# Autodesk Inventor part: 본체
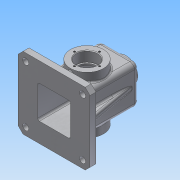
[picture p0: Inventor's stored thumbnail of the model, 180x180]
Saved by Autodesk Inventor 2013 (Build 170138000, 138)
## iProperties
Created: 2018-10
Part Number: 본체
Material: 알루미늄 6061
Document SubType Name: Modeling
Designer: Administrator
Density: 2.71 g/cm^3
Mass: 797.172 g
Surface Area: 899.5 cm^2
Volume: 294.159 cm^3
Author: Administrator
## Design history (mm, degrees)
sketch "스케치1"
  geometry: L1 (-32.5, -32.5)-(32.5, -32.5); L2 (32.5, -32.5)-(32.5, 32.5); L3 (32.5, 32.5)-(-32.5, 32.5); L4 (-32.5, 32.5)-(-32.5, -32.5); L5 (-32.5, -32.5)-(32.5, 32.5); L6 (32.5, -32.5)-(-32.5, 32.5); 1 further point
  constraints: 12 end point, 2 midpoint, 2 parallel, 1 horizontal, 1 perpendicular
  dimensions: "d0" = 65 distance of L3.end L2.end; "d1" = 65 distance of L2.end L1.end
extrude "돌출1" new body sketch "스케치1" stored distance "d2" = 110; taper "d3" = 0 deg
sketch "스케치2"
  geometry: L1 (-27.5, -27.5)-(27.5, -27.5); L2 (27.5, -27.5)-(27.5, 27.5); L3 (27.5, 27.5)-(-27.5, 27.5); L4 (-27.5, 27.5)-(-27.5, -27.5); L5 (-27.5, -27.5)-(27.5, 27.5); L6 (27.5, -27.5)-(-27.5, 27.5); 1 further point
  constraints: 12 end point, 2 midpoint, 2 parallel, 1 horizontal, 1 perpendicular
  dimensions: "d4" = 55 distance of L3.end L2.end; "d5" = 55 distance of L1.end L2.end
extrude "돌출2" cut sketch "스케치2" distance "d6" = 105; taper "d7" = 0 deg
node "작업 평면1"
sketch "스케치3"
  geometry: C1 r 20 at (0, 0); 1 further point
  constraints: 1 centre point, 1 coincident
  dimensions: "d9" = 40 diameter of C1
extrude "돌출3" join sketch "스케치3" stored distance "d10" = 105; taper "d11" = 7 deg
fillet "모깎기2" dims "d13" = 8
fillet "모깎기3" dims "d14" = 3
fillet "모깎기4" dims "d15" = 3
hole "구멍1" diameter "d18" = 22.835; stored, may be unused: countersink angle "d22" = 90 deg, drill point angle "d24" = 118 deg; dims "d16" = 10, "d17" = 10, "d19" = 6, "d20" = 4, "d21" = 2, "d23" = 8
sketch "스케치8"
  geometry: C1 r 27.5 at (32.5, 55); 1 further point
  constraints: 1 centre point, 1 coincident
  dimensions: "d45" = 55 diameter of C1
extrude "돌출7" join sketch "스케치8" distance "d46" = 15; taper "d47" = 0 deg
hole "구멍4" diameter "d59" = 30; stored, may be unused: countersink angle "d63" = 90 deg, drill point angle "d65" = 0 deg; dims "d57" = 10, "d58" = 10, "d60" = 8, "d61" = 35, "d62" = 17, "d64" = 20
sketch "스케치9"
  geometry: C1 r 17.5 at (0, 0) reference; 1 further point
  constraints: 1 vertical alignment
  dimensions: "d66" = 21 distance of C1.centre point (0, 21)
hole "구멍5" sketch "스케치9" at (0, 21) diameter "d67" = 3.242; stored, may be unused: countersink angle "d71" = 90 deg, drill point angle "d73" = 118 deg; dims "d68" = 8, "d69" = 35, "d70" = 17, "d72" = 10
sketch "스케치10"
  geometry: L1 (32.5, -32.5)-(32.5, 32.5) reference; L2 (32.5, 32.5)-(-32.5, 32.5) reference; L3 (-32.5, 32.5)-(-32.5, -32.5) reference; L4 (-32.5, -32.5)-(32.5, -32.5) reference; L5 (-60, -60)-(60, -60); L6 (60, -60)-(60, 60); L7 (60, 60)-(-60, 60); L8 (-60, 60)-(-60, -60); L9 (-60, -60)-(60, 60); L10 (60, -60)-(-60, 60); 1 further point
  constraints: 12 end point, 2 midpoint, 2 parallel, 1 horizontal, 1 perpendicular
  dimensions: "d77" = 120 distance of L7.end L6.end; "d78" = 120 distance of L6.end L5.end
extrude "돌출8" join sketch "스케치10" distance "d79" = 10; taper "d80" = 0 deg
chamfer "모따기1" distance "d81" = 8; stored, may be unused: second distance "d82" = 2, angle "d83" = 45 deg
sketch "스케치12"
  geometry: L1 (44.625, -25.86)-(48, -45); L2 (52, -45)-(60, -45) reference; L3 (52, -45)-(-52, -45) reference; L4 (24.5, 50)-(11.418, 50) reference; L5 (11.418, 50)-(11.418, 65) reference; L6 (11.418, 65)-(20, 65) reference; L7 (20, 65)-(21.228, 55) reference; L8 (21.228, 55)-(24.5, 55) reference; L9 (32.5, 47)-(32.5, -45) reference; L10 (32.5, -45)-(60, -45) reference; L11 (60, -45)-(60, -55) reference; L12 (60, -55)-(27.5, -55) reference; L13 (27.5, -55)-(27.5, 47) reference; L14 (-24.5, 55)-(-21.228, 55) reference; L15 (-21.228, 55)-(-20, 65) reference; L16 (-20, 65)-(-11.418, 65) reference; L17 (-11.418, 65)-(-11.418, 50) reference; L18 (-11.418, 50)-(-24.5, 50) reference; L19 (-27.5, 47)-(-27.5, -55) reference; L20 (-27.5, -55)-(-60, -55) reference; L21 (-60, -55)-(-60, -45) reference; L22 (-60, -45)-(-32.5, -45) reference; L23 (-32.5, -45)-(-32.5, 47) reference; A1 r 3 centre (24.5, 47) between (27.5, 47) and (24.5, 50) reference; A2 r 8 centre (24.5, 47) between (32.5, 47) and (24.5, 55) reference; A3 r 8 centre (-24.5, 47) between (-24.5, 55) and (-32.5, 47) reference; A4 r 3 centre (-24.5, 47) between (-24.5, 50) and (-27.5, 47) reference; 1 further point
  constraints: 2 end point, 1 point on line
  dimensions: "d89" = 12 horizontal distance of L11.end L1.end; "d90" = 10 deg angle of L11 L1
feature "리브1" sketch "스케치12" dims "d91" = 1, "d92" = 10, "d93" = 0, "d94" = 0, "d95" = 1, "d96" = 1
sketch "스케치13"
  geometry: L1 (-35.906, 42.5)-(-41.908, 42.5); L2 (-17.5, 30.5)-(-15, 30.5) reference; L3 (-15, 30.5)-(-15, 27.5) reference; L4 (-15, 27.5)-(-55, 27.5) reference; L5 (-55, 27.5)-(-55, 60) reference; L6 (-55, 60)-(-45, 60) reference; L7 (-45, 60)-(-45, 32.5) reference; L8 (-45, 32.5)-(-27.5, 32.5) reference; L9 (-27.5, 32.5)-(-27.5, 47.5) reference; L10 (-27.5, 47.5)-(-22.621, 47.5) reference; L11 (-22.621, 47.5)-(-22.621, 37.5) reference; L12 (-22.621, 37.5)-(-21, 36.526) reference; L13 (-21, 36.526)-(-19.379, 37.5) reference; L14 (-19.379, 37.5)-(-19.379, 47.5) reference; L15 (-19.379, 47.5)-(-17.5, 47.5) reference; L16 (-17.5, 47.5)-(-17.5, 30.5) reference; L17 (47, 27.5)-(15, 27.5) reference; L18 (15, 27.5)-(15, 30.5) reference; L19 (15, 30.5)-(17.5, 30.5) reference; L20 (17.5, 30.5)-(17.5, 47.5) reference; L21 (17.5, 47.5)-(19.379, 47.5) reference; L22 (19.379, 47.5)-(19.379, 37.5) reference; L23 (19.379, 37.5)-(21, 36.526) reference; L24 (21, 36.526)-(22.621, 37.5) reference; L25 (22.621, 37.5)-(22.621, 47.5) reference; L26 (22.621, 47.5)-(27.5, 47.5) reference; L27 (27.5, 47.5)-(27.5, 32.5) reference; L28 (27.5, 32.5)-(47, 32.5) reference; L29 (55, 24.5)-(55, 21.228) reference; L30 (55, 21.228)-(65, 20) reference; L31 (65, 20)-(65, 11.418) reference; L32 (65, 11.418)-(50, 11.418) reference; L33 (50, 11.418)-(50, 24.5) reference; L34 (47, -32.5)-(-45, -32.5) reference; L35 (-45, -32.5)-(-45, -60) reference; L36 (-45, -60)-(-55, -60) reference; L37 (-55, -60)-(-55, -27.5) reference; L38 (-55, -27.5)-(47, -27.5) reference; L39 (50, -24.5)-(50, -11.418) reference; L40 (50, -11.418)-(65, -11.418) reference; L41 (65, -11.418)-(65, -20) reference; L42 (65, -20)-(55, -21.228) reference; L43 (55, -21.228)-(55, -24.5) reference; A1 r 3 centre (47, 24.5) between (50, 24.5) and (47, 27.5) reference; A2 r 8 centre (47, 24.5) between (55, 24.5) and (47, 32.5) reference; A3 r 8 centre (47, -24.5) between (47, -32.5) and (55, -24.5) reference; A4 r 3 centre (47, -24.5) between (47, -27.5) and (50, -24.5) reference; 1 further point
  constraints: 2 end point, 1 horizontal
  dimensions: "d97" = 15 distance between parallel lines of L4 L1
feature "리브2" sketch "스케치13" dims "d98" = 1, "d99" = 6, "d100" = 0, "d101" = 0, "d102" = 1, "d103" = 1
sketch "스케치14"
  geometry: 5 further points
  constraints: 2 horizontal alignment, 2 vertical alignment
  dimensions: "d105" = 95 distance of point (-47.5, -47.5) point (47.5, -47.5); "d107" = 95 distance of point (47.5, -47.5) point (47.5, 47.5); "d108" = 47.5 horizontal distance of point (0, 0) point (47.5, -47.5); "d109" = 47.5 horizontal distance of point (0, 0) point (-47.5, -47.5)
hole "구멍6" sketch "스케치14" at (-47.5, -47.5), (-47.5, 47.5), (47.5, 47.5), (47.5, -47.5) diameter "d110" = 10; stored, may be unused: countersink angle "d114" = 90 deg, drill point angle "d116" = 0 deg; dims "d111" = 8, "d112" = 35, "d113" = 17, "d115" = 10
sketch "스케치15"
  geometry: L1 (0, 0)-(0, -92) reference; L2 (12.5, 18)-(52.5, 18) reference; 1 further point
  constraints: 1 other
  dimensions: "d117" = 32.5 distance from line of L1 point (32.5, -8); "d118" = 26 distance from line of point (32.5, -8) L2
feature "엠보싱1" sketch "스케치15" dims "d0" = 65, "d1" = 65, "d119" = 0.5, "d120" = 0
fillet "모깎기7" dims "d121" = 8
fillet "모깎기8" dims "d122" = 3
fillet "모깎기9" dims "d123" = 3
fillet "모깎기10" dims "d124" = 3
fillet "모깎기11" dims "d125" = 1
fillet "모깎기12" dims "d126" = 0.3
chamfer "모따기2" distance "d127" = 1; stored, may be unused: second distance "d128" = 2, angle "d129" = 45 deg
fillet "모깎기13" dims "d130" = 3
node "솔리드1"
pattern_circular "원형 패턴2" dims angle "d75" = 360 deg
mirror "대칭2"
mirror "대칭3"
mirror "대칭4"
node "절단 모서리 투영1"
node "절단 모서리 투영2"
